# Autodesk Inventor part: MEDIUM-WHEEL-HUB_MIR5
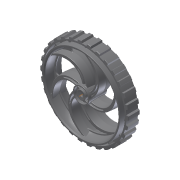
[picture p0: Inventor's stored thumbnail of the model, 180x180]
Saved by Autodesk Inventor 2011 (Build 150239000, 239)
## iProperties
Created: 2007-08
Part Number: MEDIUM-WHEEL-HUB_MIR5
Material: ABS Plastic
Document SubType Name: Modeling
Mass: 42.8255 g
Surface Area: 324.402 cm^2
Volume: 40.4014 cm^3
Density: 1.06 g/cm^3
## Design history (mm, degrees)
derived "MEDIUM-WHEEL-HUB.ipt"
  workaxis "Work Axis1"
body "Solid1"
tag "TaggingFeature2"
feature "DerivedBody::MEDIUM-WHEEL-HUB.ipt" dims "d0" = 10
